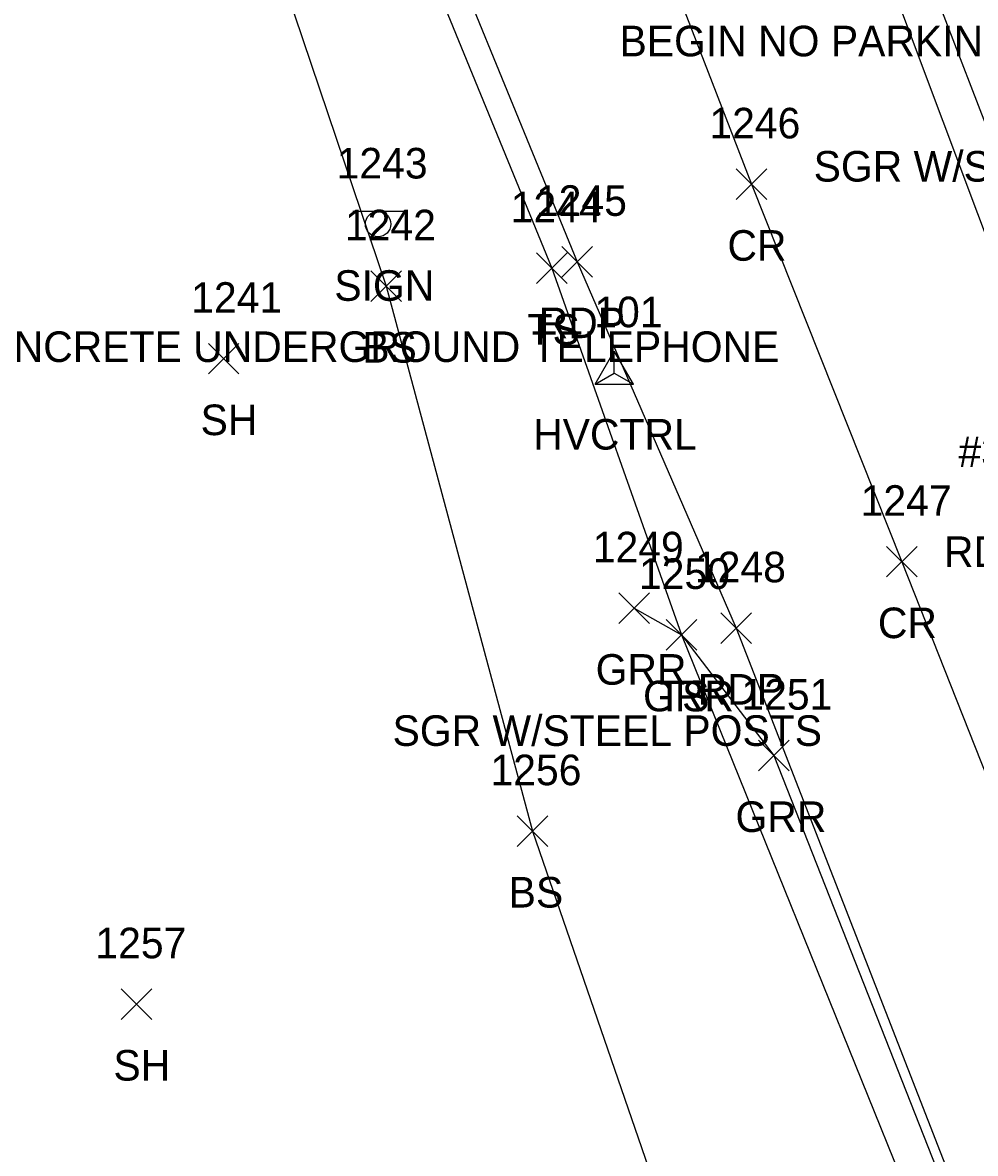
# Model space of a CAD drawing. Extents: x 1651305 to 1654558, y 539481 to 548441.
# Drawn here: x 1654251.1 to 1654313.4, y 544674.1 to 544748.1 of the extents above; entities that cross this region are included whole.
import ezdxf

# ---------------------------------------------------------------- set-up
doc = ezdxf.new("R2010")
doc.units = 0
for name, color, linetype in [('C_A', 7, 'Continuous'), ('C_I', 7, 'Continuous'), ('CPSM', 7, 'Continuous'), ('L_A', 7, 'Continuous'), ('L_I', 7, 'Continuous'), ('L_TIC', 7, 'Continuous'), ('LELB', 7, 'Continuous'), ('P_A', 7, 'Continuous'), ('P_I', 7, 'Continuous'), ('P_TIC', 7, 'Continuous'), ('PET', 7, 'Continuous'), ('PRC', 7, 'Continuous'), ('PSP', 7, 'Continuous'), ('R_A', 7, 'Continuous'), ('R_C', 7, 'Continuous'), ('R_I', 7, 'Continuous'), ('R_TIC', 7, 'Continuous'), ('RGR', 7, 'Continuous'), ('S_A', 7, 'Continuous'), ('S_C', 7, 'Continuous'), ('S_I', 7, 'Continuous'), ('SSGN', 7, 'Continuous'), ('U_C', 7, 'Continuous')]:
    doc.layers.add(name, color=color, linetype=linetype)

msp = doc.modelspace()

# ---------------------------------------------------------------- linework, layer by layer
at = {"layer": 'CPSM'}
for p, q in [((1654288.541, 544724.419), (1654289.791, 544726.584)), ((1654291.041, 544724.419), (1654289.791, 544726.584)), ((1654289.791, 544725.141), (1654289.791, 544726.584)), ((1654288.541, 544724.419), (1654289.791, 544725.141)), ((1654289.791, 544725.141), (1654289.791, 544725.141)), ((1654289.791, 544725.141), (1654291.041, 544724.419)), ((1654288.541, 544724.419), (1654291.041, 544724.419))]:
    msp.add_line(p, q, dxfattribs=at)
at = {"layer": 'L_TIC'}
for points in [[(1654284.709, 544731.002), (1654286.709, 544733.002)], [(1654286.709, 544731.002), (1654284.709, 544733.002)], [(1654273.867, 544729.828), (1654275.867, 544731.828)], [(1654275.867, 544729.828), (1654273.867, 544731.828)], [(1654263.245, 544725.087), (1654265.245, 544727.087)], [(1654265.245, 544725.087), (1654263.245, 544727.087)], [(1654293.184, 544707.026), (1654295.184, 544709.026)], [(1654295.184, 544707.026), (1654293.184, 544709.026)], [(1654283.44, 544694.192), (1654285.44, 544696.192)], [(1654285.44, 544694.192), (1654283.44, 544696.192)], [(1654257.546, 544682.874), (1654259.546, 544684.874)], [(1654259.546, 544682.874), (1654257.546, 544684.874)]]:
    msp.add_lwpolyline(points, dxfattribs=at)
at = {"layer": 'LELB'}
for points in [[(1654179.719, 544986.88), (1654191.759, 544959.884), (1654205.631, 544927.6), (1654216.28, 544901.811), (1654236.779, 544849.686), (1654250.25, 544817.938), (1654269.188, 544772.346), (1654285.709, 544732.002), (1654294.184, 544708.026), (1654311.836, 544664.341)], [(1654177.711, 544985.406), (1654186.395, 544960.29), (1654198.077, 544925.069), (1654208.776, 544901.638), (1654231.338, 544847.607), (1654245.847, 544816.464), (1654261.737, 544769.7), (1654274.867, 544730.828), (1654284.44, 544695.192), (1654297.614, 544656.977), (1654309.412, 544642.274)]]:
    msp.add_lwpolyline(points, dxfattribs=at)
at = {"layer": 'P_TIC'}
for points in [[(1654297.758, 544736.492), (1654299.758, 544738.492)], [(1654299.758, 544736.492), (1654297.758, 544738.492)], [(1654286.358, 544731.427), (1654288.358, 544733.427)], [(1654288.358, 544731.427), (1654286.358, 544733.427)], [(1654307.597, 544711.81), (1654309.597, 544713.81)], [(1654309.597, 544711.81), (1654307.597, 544713.81)], [(1654296.759, 544707.463), (1654298.759, 544709.463)], [(1654298.759, 544707.463), (1654296.759, 544709.463)]]:
    msp.add_lwpolyline(points, dxfattribs=at)
at = {"layer": 'PET'}
for points in [[(1654139.13, 545176.501), (1654150.393, 545147.194), (1654157.161, 545131.709), (1654170.764, 545099.134), (1654178.155, 545080.649), (1654186.439, 545060.962), (1654201.827, 545022.365), (1654207.176, 545004.715), (1654219.138, 544973.235), (1654242.36, 544920.072), (1654247.532, 544907.575), (1654259.279, 544878.108), (1654268.455, 544853.759), (1654271.522, 544840.232), (1654282.762, 544813.426), (1654295.449, 544782.265), (1654306.751, 544753.721), (1654320.353, 544717.464), (1654325.712, 544702.64)], [(1654112.873, 545166.538), (1654122.035, 545140.208), (1654132.622, 545111.941), (1654135.362, 545108.194), (1654138.441, 545103.483), (1654151.391, 545069.682), (1654150.584, 545065.43), (1654160.56, 545041.116), (1654174.104, 545006.911), (1654181.292, 544989.927), (1654184.888, 544987.01), (1654195.032, 544961.541), (1654207.758, 544928.164), (1654222.993, 544890.413), (1654239.031, 544850.694), (1654252.069, 544818.679), (1654270.718, 544773.03), (1654287.358, 544732.427), (1654297.759, 544708.463), (1654313.88, 544667.099), (1654319.767, 544684.597), (1654325.712, 544702.64)]]:
    msp.add_lwpolyline(points, dxfattribs=at)
at = {"layer": 'PRC'}
msp.add_lwpolyline([(1654126.316, 545171.737), (1654141.33, 545133.412), (1654151.931, 545107.487), (1654165.206, 545072.693), (1654175.565, 545046.61), (1654188.965, 545011.94), (1654198.023, 544989.456), (1654207.449, 544965.611), (1654220.746, 544933.068), (1654235.659, 544895.022), (1654251.308, 544856.189), (1654265.059, 544822.156), (1654283.023, 544778.205), (1654298.758, 544737.492), (1654308.597, 544712.81), (1654319.767, 544684.597)], dxfattribs=at)
at = {"layer": 'PSP'}
msp.add_lwpolyline([(1654296.828, 544784.807), (1654308.935, 544754.714), (1654316.682, 544734.635), (1654322.93, 544719.555), (1654325.421, 544714.063)], dxfattribs=at)
at = {"layer": 'R_TIC'}
for points in [[(1654290.084, 544708.764), (1654292.084, 544710.764)], [(1654292.084, 544708.764), (1654290.084, 544710.764)], [(1654293.184, 544707.026), (1654295.184, 544709.026)], [(1654295.184, 544707.026), (1654293.184, 544709.026)], [(1654299.23, 544699.133), (1654301.23, 544701.133)], [(1654301.23, 544699.133), (1654299.23, 544701.133)]]:
    msp.add_lwpolyline(points, dxfattribs=at)
at = {"layer": 'RGR'}
msp.add_lwpolyline([(1654291.084, 544709.764), (1654294.184, 544708.026), (1654300.23, 544700.133), (1654313.378, 544666.764)], dxfattribs=at)
at = {"layer": 'SSGN'}
for p, q in [((1654272.696, 544735.725), (1654276.03, 544735.725)), ((1654274.343, 544734.891), (1654274.343, 544734.891))]:
    msp.add_line(p, q, dxfattribs=at)
msp.add_circle((1654274.343, 544734.891), 0.833, dxfattribs=at)

# ---------------------------------------------------------------- texts
at = {"layer": 'C_A'}
msp.add_text('HVCTRL', height=2, dxfattribs=at).set_placement((1654284.484, 544720.141))
at = {"layer": 'C_I'}
msp.add_text('101', height=2, dxfattribs=at).set_placement((1654288.484, 544728.141))
at = {"layer": 'L_A'}
for s, p in [('TS', (1654284.119, 544727.002)), ('BS', (1654273.308, 544725.828)), ('SH', (1654262.733, 544721.087)), ('TS', (1654292.593, 544703.026)), ('BS', (1654282.881, 544690.192)), ('SH', (1654257.034, 544678.874))]:
    msp.add_text(s, height=2, dxfattribs=at).set_placement(p)
at = {"layer": 'L_I'}
for s, p in [('1244', (1654283.016, 544735.002)), ('1242', (1654272.174, 544733.828)), ('1241', (1654262.119, 544729.087)), ('1250', (1654291.404, 544711.026)), ('1256', (1654281.692, 544698.192)), ('1257', (1654255.853, 544686.874))]:
    msp.add_text(s, height=2, dxfattribs=at).set_placement(p)
at = {"layer": 'P_A'}
for s, p in [('CR', (1654297.191, 544732.492)), ('RDP', (1654284.847, 544727.427)), ('CR', (1654307.03, 544707.81)), ('RDP', (1654295.247, 544703.463))]:
    msp.add_text(s, height=2, dxfattribs=at).set_placement(p)
at = {"layer": 'P_I'}
for s, p in [('1246', (1654296.01, 544740.492)), ('1245', (1654284.666, 544735.427)), ('1247', (1654305.904, 544715.81)), ('1248', (1654295.066, 544711.463))]:
    msp.add_text(s, height=2, dxfattribs=at).set_placement(p)
at = {"layer": 'R_A'}
for s, p in [('RDP1 SWP ST', (1654311.353, 544712.464)), ('GRR', (1654288.572, 544704.764)), ('GRR', (1654291.672, 544703.026)), ('GRR', (1654297.718, 544695.133))]:
    msp.add_text(s, height=2, dxfattribs=at).set_placement(p)
at = {"layer": 'R_C'}
for p in [(1654302.828, 544737.668), (1654275.289, 544700.764)]:
    msp.add_text('SGR W/STEEL POSTS', height=2, dxfattribs=at).set_placement(p)
at = {"layer": 'R_I'}
for s, p in [('1249', (1654288.383, 544712.764)), ('1250', (1654291.404, 544711.026)), ('1251', (1654298.104, 544703.133))]:
    msp.add_text(s, height=2, dxfattribs=at).set_placement(p)
at = {"layer": 'S_A'}
msp.add_text('SIGN', height=2, dxfattribs=at).set_placement((1654271.481, 544729.871))
at = {"layer": 'S_C'}
for s, p in [('BEGIN NO PARKING/ SPEED LIMIT', (1654290.133, 544745.861)), ('CONCRETE UNDERGROUND TELEPHONE', (1654246.497, 544725.871))]:
    msp.add_text(s, height=2, dxfattribs=at).set_placement(p)
at = {"layer": 'S_I'}
msp.add_text('1243', height=2, dxfattribs=at).set_placement((1654271.631, 544737.871))
at = {"layer": 'U_C'}
msp.add_text('#342A/499/418', height=2, dxfattribs=at).set_placement((1654312.293, 544718.999))

doc.saveas('drawing.dxf')
